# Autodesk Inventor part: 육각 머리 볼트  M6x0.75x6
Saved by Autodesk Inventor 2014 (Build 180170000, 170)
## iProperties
Created: 2025-02
Part Number: 육각 머리 볼트  M6x0.75x6
Material: 강철, 연강
Document SubType Name: Modeling
Designer: dg
Density: 7.86 g/cm^3
Appearance: 강철
Mass: 4.02371 g
Surface Area: 4.11549 cm^2
Volume: 0.511923 cm^3
Author: jhkim
Description: 6각 머리 볼트 및 6각 머리 나사
Creation Date: 2025-01-06
Sending System: Autodesk Inventor 2025
Preprocessor: ST-DEVELOPER v20
Author: dg
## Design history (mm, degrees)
node "육각 머리 볼트  M6x0.75x61"
body "Solid1"
node "기준1"
